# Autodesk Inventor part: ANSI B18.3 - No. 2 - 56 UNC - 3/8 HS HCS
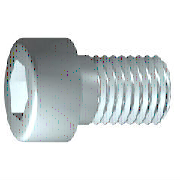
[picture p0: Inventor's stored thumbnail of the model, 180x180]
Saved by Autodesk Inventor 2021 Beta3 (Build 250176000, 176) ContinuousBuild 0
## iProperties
IsCustomPart: 0
Created: 2012-02
Part Number: ANSI B18.3 - No. 2 - 56 UNC - 3/8 HS HCS
Material: Steel, Mild
Description: Hexagon Socket Head Cap Screw
Document SubType Name: Modeling
Standard: ANSI B18.3
Designer: John
Standard Revision: 2003
Standards Organization: ANSI
Language: en-US
Size Designation: No. 2 - 56 UNC - 3/8
Categories: <MemberInstance><Categories><Category DisplayName="Fasteners" InternalName="e4da775c-781d-43d5-af7c-5136215cf5a6" Mnemonic="FSTN"><Category DisplayName="Bolts"
Density: 1 g/cm^3
Appearance: Steel
Author: John
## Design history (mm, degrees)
sketch "Sketch1"
  geometry: L1 (-0.559, 0)-(9.525, 0); L2 (9.525, 0)-(9.525, 1.092); L3 (9.525, 1.092)-(1.134, 1.092); L4 (1.134, 1.092)-(0, 1.092); L5 (0, 1.092)-(0, 1.092); L6 (0, 1.092)-(0, 1.778); L7 (0, 1.778)-(-2.184, 1.778); L8 (-2.184, 1.778)-(-2.184, 1.144); L9 (-2.184, 1.144)-(-1.219, 1.144); L10 (-1.219, 1.144)-(-0.559, 0); L11 (-4.526, 0)-(11.867, 0) reference; L12 (0, -0.356)-(0, 2.134) reference; L13 (1.134, 1.092)-(0, 1.092)
  constraints: 22 end point, 6 parallel, 2 collinear, 2 perpendicular, 1 horizontal, 1 point on line
  dimensions: "d1" = 8.39094 distance from line of L3.end L2 (= GEL); "d2" = 1.13396 distance of L4.end L3.end (computed from GAL); "d3" = 2.1844 distance between parallel lines of L8 L6 (= KOH); "d4" = 0.9652 distance of L8.end L9.end (= INTI); "d5" = 60 deg angle of L10 L1; "d6" = 2.1844 diameter of L3 L1 (= GD); "d7" = 2.1844 diameter of L5 L1 (= BDM); "d8" = 2.28769 diameter of L9 L1 (= 1.1547 x SW); "d9" = 3.556 diameter of L7 L1 (= KOD); "d26" = 9.525 distance between parallel lines of L12 L2 (= NLG)
revolve "Body" sketch "Sketch1" stored, may be unused: angle "d10" = 90 deg
sketch "Sketch2"
  geometry: L1 (0, -2.489)-(0, 2.489) reference; L2 (-2.489, 0)-(2.489, 0) reference; L3 (1.144, 0)-(0.572, -0.991); L4 (0.572, -0.991)-(-0.572, -0.991); L5 (-0.572, -0.991)-(-1.144, 0); L6 (-1.144, 0)-(-0.572, 0.991); L7 (-0.572, 0.991)-(0.572, 0.991); L8 (0.572, 0.991)-(1.144, 0); 2 further points
  constraints: 12 end point, 1 coincident, 1 horizontal alignment, 1 point on line, 12 other
extrude "Slot" join sketch "Sketch2" stored distance "d11" = 10; taper "d12" = 0 deg
workplane "Work Plane1"
fillet "Fillet2" dims "d30" = 0.0762 (= R)
body "Solid1"
fillet "Fillet1" dims "d17" = 0.2032 (= RR)
feature "Thread" dims "d13" = 8.39094 (= GEL), "d14" = 0
chamfer "Chamfer1" distance "d15" = 0.26924 (= -0.5 x SPD + 0.5 x GD); stored, may be unused: second distance "d16" = 0.26924 (= GUL), angle "d27" = 45 deg
other parameters: "GD" = 2.1844 [user parameter; used in 2 equation terms], "NLG" = 9.525 [user parameter; used in 1 equation term], "GEL" = 8.39094 [user parameter; used in 2 equation terms], "KOD" = 3.556 [user parameter; used in 1 equation term], "KOH" = 2.1844 [user parameter; used in 1 equation term], "INTI" = 0.9652 [user parameter; used in 1 equation term], "GAL" = 1.13386 [user parameter; used in 1 equation term], "GUL" = 0.26924 [user parameter; used in 1 equation term], "BDM" = 2.1844 [user parameter; used in 1 equation term], "SW" = 1.9812 [user parameter; used in 2 equation terms], "RR" = 0.2032 [user parameter; used in 1 equation term], "SPD" = 1.64592 [user parameter; used in 2 equation terms], "d19" = 0, "d28" = 0, "d29" = 0, "R" = 0.0762 [user parameter; used in 1 equation term], "PHH" = 0.0762 [user parameter], "GD1" = 1.64592 (= SPD) [user parameter], "THREADDIA" = 2.1844 [user parameter], "FAWI" = 45 deg [user parameter], "PTC" = 0.45357 (computed from TPU) [user parameter], "KOH1" = 1.9558 [user parameter], "NND" = 2.1844 [user parameter], "TOA" = 30 deg [user parameter], "E0" = 2.28829 (= 1.155 x SW) [user parameter]
